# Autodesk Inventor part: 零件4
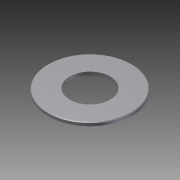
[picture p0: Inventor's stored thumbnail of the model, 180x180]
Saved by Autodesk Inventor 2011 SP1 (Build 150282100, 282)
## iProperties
Created: 2014-02
Part Number: 零件4
Document SubType Name: Modeling
Designer: yn
Density: 1 g/cm^3
Author: yn
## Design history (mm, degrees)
sketch "草图1"
  geometry: C1 r 6 at (0, 0); C2 r 12.503 at (0, 0); 1 further point
  constraints: 2 centre point, 2 coincident
  dimensions: "d0" = 12 diameter of C1
extrude "拉伸1" new body sketch "草图1" distance "d1" = 1; taper "d2" = 0 deg
chamfer "倒角1" distance "d3" = 0.2; stored, may be unused: second distance "d4" = 2, angle "d5" = 45 deg
node "实体1"
